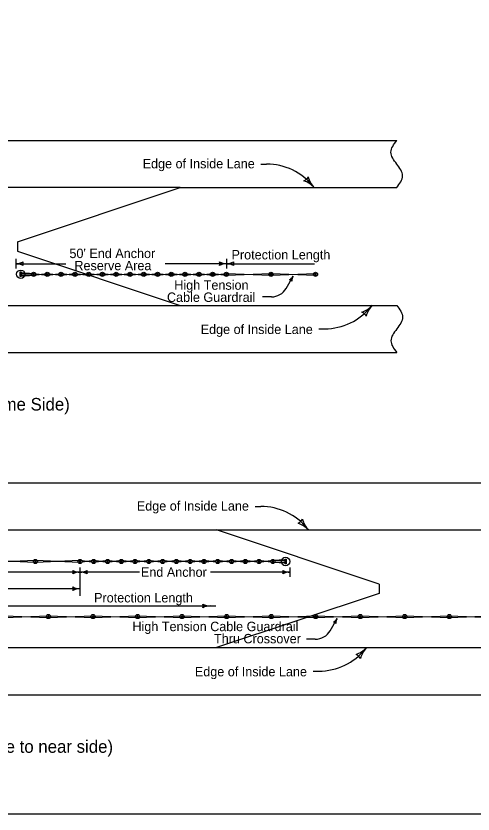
# Model space of a CAD drawing. Extents: x 10133 to 81668, y 7924 to 11018.
# Drawn here: x 11106 to 11688, y 7924 to 8940 of the extents above; entities that cross this region are included whole.
import ezdxf

# ---------------------------------------------------------------- set-up
doc = ezdxf.new("R2010")
doc.units = 0
for name, color, linetype in [('dsnCellElements', 7, 'Continuous'), ('DsnShtRevisedText', 7, 'Continuous'), ('dsnStdDimension', 7, 'Continuous'), ('Level 8', 7, 'Continuous'), ('SheetBorder', 7, 'Continuous')]:
    doc.layers.add(name, color=color, linetype=linetype)

msp = doc.modelspace()

# ---------------------------------------------------------------- linework, layer by layer
at = {"layer": 'dsnCellElements'}
for p, q in [((11112.3, 8613.7), (11129, 8612.5)), ((11112.3, 8612.5), (11128.1, 8612.5)), ((11112.3, 8610.3), (11128.1, 8610.3)), ((11112.3, 8609.1), (11129, 8610.3)), ((11129, 8612.5), (11145.6, 8610.3)), ((11129, 8610.3), (11145.6, 8612.5)), ((11146.5, 8612.5), (11163.2, 8610.3)), ((11146.5, 8610.3), (11163.2, 8612.5)), ((11164.1, 8612.5), (11180.7, 8610.3)), ((11164.1, 8610.3), (11180.7, 8612.5)), ((11181.6, 8612.5), (11198.3, 8610.3)), ((11181.6, 8610.3), (11198.3, 8612.5)), ((11199.2, 8612.5), (11215.8, 8610.3)), ((11199.2, 8610.3), (11215.8, 8612.5)), ((11216.7, 8612.5), (11233.4, 8610.3)), ((11216.7, 8610.3), (11233.4, 8612.5)), ((11234.3, 8610.3), (11250.9, 8612.5)), ((11234.3, 8612.5), (11250.9, 8610.3)), ((11251.8, 8612.5), (11268.5, 8610.3)), ((11251.8, 8610.3), (11268.5, 8612.5)), ((11269.4, 8612.5), (11286, 8610.3)), ((11269.4, 8610.3), (11286, 8612.5)), ((11286.9, 8612.5), (11303.6, 8610.3)), ((11286.9, 8610.3), (11303.6, 8612.5)), ((11304.5, 8612.5), (11321.1, 8610.3)), ((11304.5, 8610.3), (11321.1, 8612.5)), ((11322, 8612.5), (11338.6, 8610.3)), ((11322, 8610.3), (11338.6, 8612.5)), ((11339.6, 8612.5), (11356.2, 8610.3)), ((11339.6, 8610.3), (11356.2, 8612.5)), ((11357.1, 8612.5), (11373.7, 8610.3)), ((11357.1, 8610.3), (11373.7, 8612.5)), ((11374.7, 8612.5), (11430.4, 8610.3)), ((11374.7, 8610.3), (11430.4, 8612.5)), ((11431.4, 8612.5), (11487.1, 8610.3)), ((11431.4, 8610.3), (11487.1, 8612.5)), ((11130.5, 8244.5), (11074.7, 8246.8)), ((11130.5, 8246.8), (11074.7, 8244.5)), ((11187.2, 8244.5), (11131.4, 8246.8)), ((11187.2, 8246.8), (11131.4, 8244.5)), ((11204.8, 8244.5), (11188.1, 8246.8)), ((11204.8, 8246.8), (11188.1, 8244.5)), ((11222.3, 8244.5), (11205.7, 8246.8)), ((11222.3, 8246.8), (11205.7, 8244.5)), ((11239.9, 8244.5), (11223.2, 8246.8)), ((11239.9, 8246.8), (11223.2, 8244.5)), ((11257.4, 8244.5), (11240.8, 8246.8)), ((11257.4, 8246.8), (11240.8, 8244.5)), ((11275, 8244.5), (11258.3, 8246.8)), ((11275, 8246.8), (11258.3, 8244.5)), ((11292.5, 8244.5), (11275.9, 8246.8)), ((11292.5, 8246.8), (11275.9, 8244.5)), ((11310, 8244.5), (11293.4, 8246.8)), ((11310, 8246.8), (11293.4, 8244.5)), ((11327.6, 8246.8), (11311, 8244.5)), ((11327.6, 8244.5), (11311, 8246.8)), ((11345.1, 8244.5), (11328.5, 8246.8)), ((11345.1, 8246.8), (11328.5, 8244.5)), ((11362.7, 8244.5), (11346.1, 8246.8)), ((11362.7, 8246.8), (11346.1, 8244.5)), ((11380.2, 8244.5), (11363.6, 8246.8)), ((11380.2, 8246.8), (11363.6, 8244.5)), ((11397.8, 8244.5), (11381.2, 8246.8)), ((11397.8, 8246.8), (11381.2, 8244.5)), ((11415.3, 8244.5), (11398.7, 8246.8)), ((11415.3, 8246.8), (11398.7, 8244.5)), ((11432.9, 8244.5), (11416.3, 8246.8)), ((11432.9, 8246.8), (11416.3, 8244.5)), ((11449.6, 8247.9), (11432.9, 8246.8)), ((11449.6, 8243.3), (11432.9, 8244.5)), ((11449.6, 8246.8), (11433.8, 8246.8)), ((11449.6, 8244.5), (11433.8, 8244.5)), ((11091.4, 8176.6), (11147.2, 8174.3)), ((11091.4, 8174.3), (11147.2, 8176.6)), ((11148.1, 8176.6), (11203.9, 8174.3)), ((11148.1, 8174.3), (11203.9, 8176.6)), ((11204.8, 8176.6), (11260.6, 8174.3)), ((11204.8, 8174.3), (11260.6, 8176.6)), ((11261.5, 8176.6), (11317.3, 8174.3)), ((11261.5, 8174.3), (11317.3, 8176.6)), ((11318.2, 8176.6), (11374, 8174.3)), ((11318.2, 8174.3), (11374, 8176.6)), ((11374.9, 8176.6), (11430.7, 8174.3)), ((11374.9, 8174.3), (11430.7, 8176.6)), ((11431.6, 8176.6), (11487.4, 8174.3)), ((11431.6, 8174.3), (11487.4, 8176.6)), ((11488.3, 8176.6), (11544.1, 8174.3)), ((11488.3, 8174.3), (11544.1, 8176.6)), ((11545, 8176.6), (11600.8, 8174.3)), ((11545, 8174.3), (11600.8, 8176.6)), ((11601.7, 8176.6), (11657.5, 8174.3)), ((11601.7, 8174.3), (11657.5, 8176.6)), ((11658.4, 8176.6), (11714.2, 8174.3)), ((11658.4, 8174.3), (11714.2, 8176.6))]:
    msp.add_line(p, q, dxfattribs=at)
for points in [[(11111.7, 8608.4), (11111.7, 8614.4), (11112.9, 8614.4), (11112.9, 8608.4)], [(11128.1, 8610.3), (11128.1, 8612.5), (11129, 8612.5), (11129, 8610.3)], [(11145.6, 8610.3), (11145.6, 8612.5), (11146.5, 8612.5), (11146.5, 8610.3)], [(11163.2, 8610.3), (11163.2, 8612.5), (11164.1, 8612.5), (11164.1, 8610.3)], [(11180.7, 8610.3), (11180.7, 8612.5), (11181.6, 8612.5), (11181.6, 8610.3)], [(11198.3, 8610.3), (11198.3, 8612.5), (11199.2, 8612.5), (11199.2, 8610.3)], [(11215.8, 8610.3), (11215.8, 8612.5), (11216.7, 8612.5), (11216.7, 8610.3)], [(11233.4, 8610.3), (11233.4, 8612.5), (11234.3, 8612.5), (11234.3, 8610.3)], [(11250.9, 8610.3), (11250.9, 8612.5), (11251.8, 8612.5), (11251.8, 8610.3)], [(11268.5, 8610.3), (11268.5, 8612.5), (11269.4, 8612.5), (11269.4, 8610.3)], [(11286, 8610.3), (11286, 8612.5), (11286.9, 8612.5), (11286.9, 8610.3)], [(11303.6, 8610.3), (11303.6, 8612.5), (11304.5, 8612.5), (11304.5, 8610.3)], [(11321.1, 8610.3), (11321.1, 8612.5), (11322, 8612.5), (11322, 8610.3)], [(11338.6, 8610.3), (11338.6, 8612.5), (11339.6, 8612.5), (11339.6, 8610.3)], [(11356.2, 8610.3), (11356.2, 8612.5), (11357.1, 8612.5), (11357.1, 8610.3)], [(11373.7, 8610.3), (11373.7, 8612.5), (11374.7, 8612.5), (11374.7, 8610.3)], [(11373.7, 8610.3), (11373.7, 8612.5), (11374.7, 8612.5), (11374.7, 8610.3)], [(11430.4, 8610.3), (11430.4, 8612.5), (11431.4, 8612.5), (11431.4, 8610.3)], [(11430.4, 8610.3), (11430.4, 8612.5), (11431.4, 8612.5), (11431.4, 8610.3)], [(11487.1, 8610.3), (11487.1, 8612.5), (11488.1, 8612.5), (11488.1, 8610.3)], [(11131.4, 8246.8), (11131.4, 8244.5), (11130.5, 8244.5), (11130.5, 8246.8)], [(11131.4, 8246.8), (11131.4, 8244.5), (11130.5, 8244.5), (11130.5, 8246.8)], [(11188.1, 8246.8), (11188.1, 8244.5), (11187.2, 8244.5), (11187.2, 8246.8)], [(11188.1, 8246.8), (11188.1, 8244.5), (11187.2, 8244.5), (11187.2, 8246.8)], [(11205.7, 8246.8), (11205.7, 8244.5), (11204.8, 8244.5), (11204.8, 8246.8)], [(11223.2, 8246.8), (11223.2, 8244.5), (11222.3, 8244.5), (11222.3, 8246.8)], [(11240.8, 8246.8), (11240.8, 8244.5), (11239.9, 8244.5), (11239.9, 8246.8)], [(11258.3, 8246.8), (11258.3, 8244.5), (11257.4, 8244.5), (11257.4, 8246.8)], [(11275.9, 8246.8), (11275.9, 8244.5), (11275, 8244.5), (11275, 8246.8)], [(11293.4, 8246.8), (11293.4, 8244.5), (11292.5, 8244.5), (11292.5, 8246.8)], [(11311, 8246.8), (11311, 8244.5), (11310, 8244.5), (11310, 8246.8)], [(11328.5, 8246.8), (11328.5, 8244.5), (11327.6, 8244.5), (11327.6, 8246.8)], [(11346.1, 8246.8), (11346.1, 8244.5), (11345.1, 8244.5), (11345.1, 8246.8)], [(11363.6, 8246.8), (11363.6, 8244.5), (11362.7, 8244.5), (11362.7, 8246.8)], [(11381.2, 8246.8), (11381.2, 8244.5), (11380.2, 8244.5), (11380.2, 8246.8)], [(11398.7, 8246.8), (11398.7, 8244.5), (11397.8, 8244.5), (11397.8, 8246.8)], [(11416.3, 8246.8), (11416.3, 8244.5), (11415.3, 8244.5), (11415.3, 8246.8)], [(11433.8, 8246.8), (11433.8, 8244.5), (11432.9, 8244.5), (11432.9, 8246.8)], [(11450.2, 8248.6), (11450.2, 8242.6), (11449, 8242.6), (11449, 8248.6)], [(11147.2, 8174.3), (11147.2, 8176.6), (11148.1, 8176.6), (11148.1, 8174.3)], [(11147.2, 8174.3), (11147.2, 8176.6), (11148.1, 8176.6), (11148.1, 8174.3)], [(11203.9, 8174.3), (11203.9, 8176.6), (11204.8, 8176.6), (11204.8, 8174.3)], [(11203.9, 8174.3), (11203.9, 8176.6), (11204.8, 8176.6), (11204.8, 8174.3)], [(11260.6, 8174.3), (11260.6, 8176.6), (11261.5, 8176.6), (11261.5, 8174.3)], [(11260.6, 8174.3), (11260.6, 8176.6), (11261.5, 8176.6), (11261.5, 8174.3)], [(11317.3, 8174.3), (11317.3, 8176.6), (11318.2, 8176.6), (11318.2, 8174.3)], [(11317.3, 8174.3), (11317.3, 8176.6), (11318.2, 8176.6), (11318.2, 8174.3)], [(11374, 8174.3), (11374, 8176.6), (11374.9, 8176.6), (11374.9, 8174.3)], [(11374, 8174.3), (11374, 8176.6), (11374.9, 8176.6), (11374.9, 8174.3)], [(11430.7, 8174.3), (11430.7, 8176.6), (11431.6, 8176.6), (11431.6, 8174.3)], [(11430.7, 8174.3), (11430.7, 8176.6), (11431.6, 8176.6), (11431.6, 8174.3)], [(11487.4, 8174.3), (11487.4, 8176.6), (11488.3, 8176.6), (11488.3, 8174.3)], [(11487.4, 8174.3), (11487.4, 8176.6), (11488.3, 8176.6), (11488.3, 8174.3)], [(11544.1, 8174.3), (11544.1, 8176.6), (11545, 8176.6), (11545, 8174.3)], [(11544.1, 8174.3), (11544.1, 8176.6), (11545, 8176.6), (11545, 8174.3)], [(11600.8, 8174.3), (11600.8, 8176.6), (11601.7, 8176.6), (11601.7, 8174.3)], [(11600.8, 8174.3), (11600.8, 8176.6), (11601.7, 8176.6), (11601.7, 8174.3)], [(11657.5, 8174.3), (11657.5, 8176.6), (11658.4, 8176.6), (11658.4, 8174.3)], [(11657.5, 8174.3), (11657.5, 8176.6), (11658.4, 8176.6), (11658.4, 8174.3)]]:
    msp.add_lwpolyline(points, close=True, dxfattribs=at)
for centre, radius in [((11112.3, 8611.4), 5.4), ((11128.6, 8611.4), 2.66), ((11146.1, 8611.4), 2.66), ((11163.7, 8611.4), 2.66), ((11181.2, 8611.4), 2.66), ((11198.8, 8611.4), 2.66), ((11216.3, 8611.4), 2.66), ((11233.8, 8611.4), 2.66), ((11251.4, 8611.4), 2.66), ((11268.9, 8611.4), 2.66), ((11286.5, 8611.4), 2.66), ((11304, 8611.4), 2.66), ((11321.5, 8611.4), 2.66), ((11339.1, 8611.4), 2.66), ((11356.6, 8611.4), 2.66), ((11374.2, 8611.4), 2.66), ((11374.2, 8611.4), 2.66), ((11430.9, 8611.4), 2.66), ((11430.9, 8611.4), 2.66), ((11487.6, 8611.4), 2.66), ((11131, 8245.6), 2.66), ((11131, 8245.6), 2.66), ((11187.7, 8245.6), 2.66), ((11187.7, 8245.6), 2.66), ((11205.2, 8245.6), 2.66), ((11222.8, 8245.6), 2.66), ((11240.3, 8245.6), 2.66), ((11257.9, 8245.6), 2.66), ((11275.4, 8245.6), 2.66), ((11292.9, 8245.6), 2.66), ((11310.5, 8245.6), 2.66), ((11328, 8245.6), 2.66), ((11345.6, 8245.6), 2.66), ((11363.1, 8245.6), 2.66), ((11380.7, 8245.6), 2.66), ((11398.2, 8245.6), 2.66), ((11415.8, 8245.6), 2.66), ((11433.3, 8245.6), 2.66), ((11449.6, 8245.6), 5.4), ((11147.6, 8175.5), 2.66), ((11147.6, 8175.5), 2.66), ((11204.3, 8175.5), 2.66), ((11204.3, 8175.5), 2.66), ((11261, 8175.5), 2.66), ((11261, 8175.5), 2.66), ((11317.7, 8175.5), 2.66), ((11317.7, 8175.5), 2.66), ((11374.5, 8175.5), 2.66), ((11374.5, 8175.5), 2.66), ((11431.2, 8175.5), 2.66), ((11431.2, 8175.5), 2.66), ((11487.9, 8175.5), 2.66), ((11487.9, 8175.5), 2.66), ((11544.6, 8175.5), 2.66), ((11544.6, 8175.5), 2.66), ((11601.3, 8175.5), 2.66), ((11601.3, 8175.5), 2.66), ((11658, 8175.5), 2.66), ((11658, 8175.5), 2.66)]:
    msp.add_circle(centre, radius, dxfattribs=at)
at = {"layer": 'DsnShtRevisedText'}
for p, q in [((11418, 8751.7), (11425.4, 8751.7)), ((11106.2, 8630.9), (11106.2, 8618.9)), ((11374.3, 8630.9), (11374.3, 8618.9)), ((11106.2, 8624.9), (11169.5, 8624.9)), ((11374.3, 8624.9), (11296.4, 8624.9)), ((11374.3, 8624.9), (11486.2, 8624.5)), ((11450.3, 8593.4), (11459.2, 8609.1)), ((11431.5, 8582.6), (11420.3, 8582.6)), ((11491.9, 8542), (11499.3, 8542)), ((11410.6, 8315.7), (11418, 8315.7)), ((11187.7, 8238.1), (11187.7, 8201.9)), ((11455, 8238.1), (11455, 8226.1)), ((11187.7, 8232.1), (10723.3, 8232.1)), ((11263.7, 8232.1), (11187.7, 8232.1)), ((11455, 8232.1), (11353.9, 8232.1)), ((11187.7, 8210.9), (11053.8, 8210.9)), ((10864.1, 8189), (11324.5, 8189)), ((11324.5, 8189), (11360.6, 8189)), ((11506.2, 8157.5), (11515.1, 8173.1)), ((11487.4, 8146.7), (11476.2, 8146.7)), ((11484.5, 8106), (11492, 8106))]:
    msp.add_line(p, q, dxfattribs=at)
for centre, radius, start, end in [((11425.4, 8675.5), 76.2, 39.0106, 90), ((11467.4, 8741.7), 12.5, 295.2639, 330.7306), ((11462.3, 8699.8), 32.4, 42.9973, 71.0698), ((11509.6, 8743.9), 32.4, 194.9248, 222.9973), ((11106.2, 8644.1), 19.1, 270, 298.0725), ((11106.2, 8605.8), 19.1, 61.9275, 90), ((11122.2, 8624.9), 7.39, 162.2666, 197.7334), ((11358.3, 8624.9), 7.39, 342.2667, 17.7334), ((11374.3, 8644.1), 19.1, 241.9275, 270), ((11374.3, 8605.8), 19.1, 90, 118.0725), ((11374.3, 8644.1), 19.1, 270, 298.0725), ((11374.3, 8605.8), 19.1, 61.9275, 90), ((11390.3, 8624.9), 7.39, 162.2666, 197.7334), ((11447.5, 8615.9), 13.6, 301.6962, 329.7686), ((11471, 8602.2), 13.6, 149.7686, 177.8411), ((11453.5, 8599.2), 5.25, 42.0353, 77.502), ((11431.5, 8604.4), 21.8, 270, 329.7757), ((11499.3, 8618.2), 76.2, 270, 320.9894), ((11536.2, 8593.9), 32.4, 288.9302, 317.0027), ((11583.5, 8549.8), 32.4, 137.0027, 165.0752), ((11541.3, 8552), 12.5, 29.2694, 64.7361), ((11418, 8239.6), 76.2, 39.0106, 90), ((11460.1, 8305.7), 12.5, 295.2639, 330.7306), ((11454.9, 8263.8), 32.4, 42.9973, 71.0698), ((11502.2, 8308), 32.4, 194.9248, 222.9973), ((11171.6, 8232.1), 7.39, 342.2667, 17.7334), ((11187.7, 8251.2), 19.1, 241.9275, 270), ((11187.7, 8251.2), 19.1, 270, 298.0725), ((11203.7, 8232.1), 7.39, 162.2666, 197.7334), ((11439, 8232.1), 7.39, 342.2667, 17.7334), ((11455, 8251.2), 19.1, 241.9275, 270), ((11187.7, 8213), 19.1, 90, 118.0725), ((11187.7, 8213), 19.1, 61.9275, 90), ((11455, 8213), 19.1, 90, 118.0725), ((11171.6, 8210.9), 7.39, 342.2667, 17.7334), ((11187.7, 8230), 19.1, 241.9275, 270), ((11187.7, 8191.8), 19.1, 90, 118.0725), ((11337.2, 8189), 7.39, 342.2666, 17.7333), ((11353.3, 8208.1), 19.1, 241.9275, 270), ((11353.3, 8169.9), 19.1, 90, 118.0725), ((11503.4, 8180), 13.6, 301.6962, 329.7686), ((11526.9, 8166.3), 13.6, 149.7686, 177.8411), ((11509.4, 8163.3), 5.25, 42.0353, 77.502), ((11487.4, 8168.4), 21.8, 270, 329.7757), ((11492, 8182.2), 76.2, 270, 320.9894), ((11528.8, 8158), 32.4, 288.9302, 317.0027), ((11576.2, 8113.8), 32.4, 137.0027, 165.0752), ((11534, 8116), 12.5, 29.2694, 64.7361)]:
    msp.add_arc(centre, radius, start, end, dxfattribs=at)
at = {"layer": 'dsnStdDimension'}
for p, q in [((10475.5, 8781.8), (11591.1, 8781.8)), ((11315.3, 8721.8), (10751.3, 8721.8)), ((11108.3, 8652.8), (11315.3, 8721.8)), ((11312.2, 8721.8), (11591.1, 8721.8)), ((11108.3, 8652.8), (11108.3, 8640.8)), ((11108.3, 8640.8), (11315.3, 8571.8)), ((10754.4, 8571.8), (11315.3, 8571.8)), ((11315.3, 8571.8), (11591.1, 8571.8)), ((10475.5, 8511.8), (11591.1, 8511.8)), ((10468.1, 8345.9), (11953.1, 8345.9)), ((10468.1, 8285.9), (11361.5, 8285.9)), ((11568.5, 8216.9), (11361.5, 8285.9)), ((11361.5, 8285.9), (11925.5, 8285.9)), ((11568.5, 8216.9), (11568.5, 8204.9)), ((11568.5, 8204.9), (11361.5, 8135.9)), ((10468.1, 8135.9), (11361.5, 8135.9)), ((11361.5, 8135.9), (11925.5, 8135.9)), ((10468.1, 8075.9), (11953.1, 8075.9))]:
    msp.add_line(p, q, dxfattribs=at)
for points in [[(11591.1, 8721.8), (11598.6, 8736.8), (11591.1, 8751.8), (11583.6, 8766.8), (11591.1, 8781.8)], [(11591.1, 8571.8), (11598.6, 8556.8), (11591.1, 8541.8), (11583.6, 8526.8), (11591.1, 8511.8)]]:
    msp.add_spline(points, degree=3, dxfattribs=at)
at = {"layer": 'SheetBorder'}
msp.add_lwpolyline([(10132.5, 9944), (13267.5, 9944), (13267.5, 7924), (10132.5, 7924)], close=True, dxfattribs=at)

# ---------------------------------------------------------------- texts
at = {"layer": 'DsnShtRevisedText'}
for s, p in [('Edge of Inside Lane', (11267.5, 8746.3)), ("50' End Anchor", (11174.3, 8632)), ('Protection Length', (11380.7, 8630.3)), ('Reserve Area', (11180.6, 8616.5)), ('High Tension', (11307.8, 8591.7)), ('Cable Guardrail', (11298.5, 8576.2)), ('Edge of Inside Lane', (11341.4, 8535.3)), ('Edge of Inside Lane', (11260.1, 8310.4)), ('End Anchor', (11265.3, 8226.1)), ('Protection Length', (11205.7, 8193.5)), ('High Tension Cable Guardrail', (11254.5, 8156.9)), ('Thru Crossover', (11358.4, 8141.4)), ('Edge of Inside Lane', (11334, 8099.4))]:
    msp.add_text(s, height=12, dxfattribs=at).set_placement(p)
at = {"layer": 'Level 8'}
for s, p in [('(Cable Stays on Same Side)', (10904.8, 8437.9)), ('(Cable switches from far side to near side)', (10829.1, 8002))]:
    msp.add_text(s, height=16, dxfattribs=at).set_placement(p)

doc.saveas('drawing.dxf')
